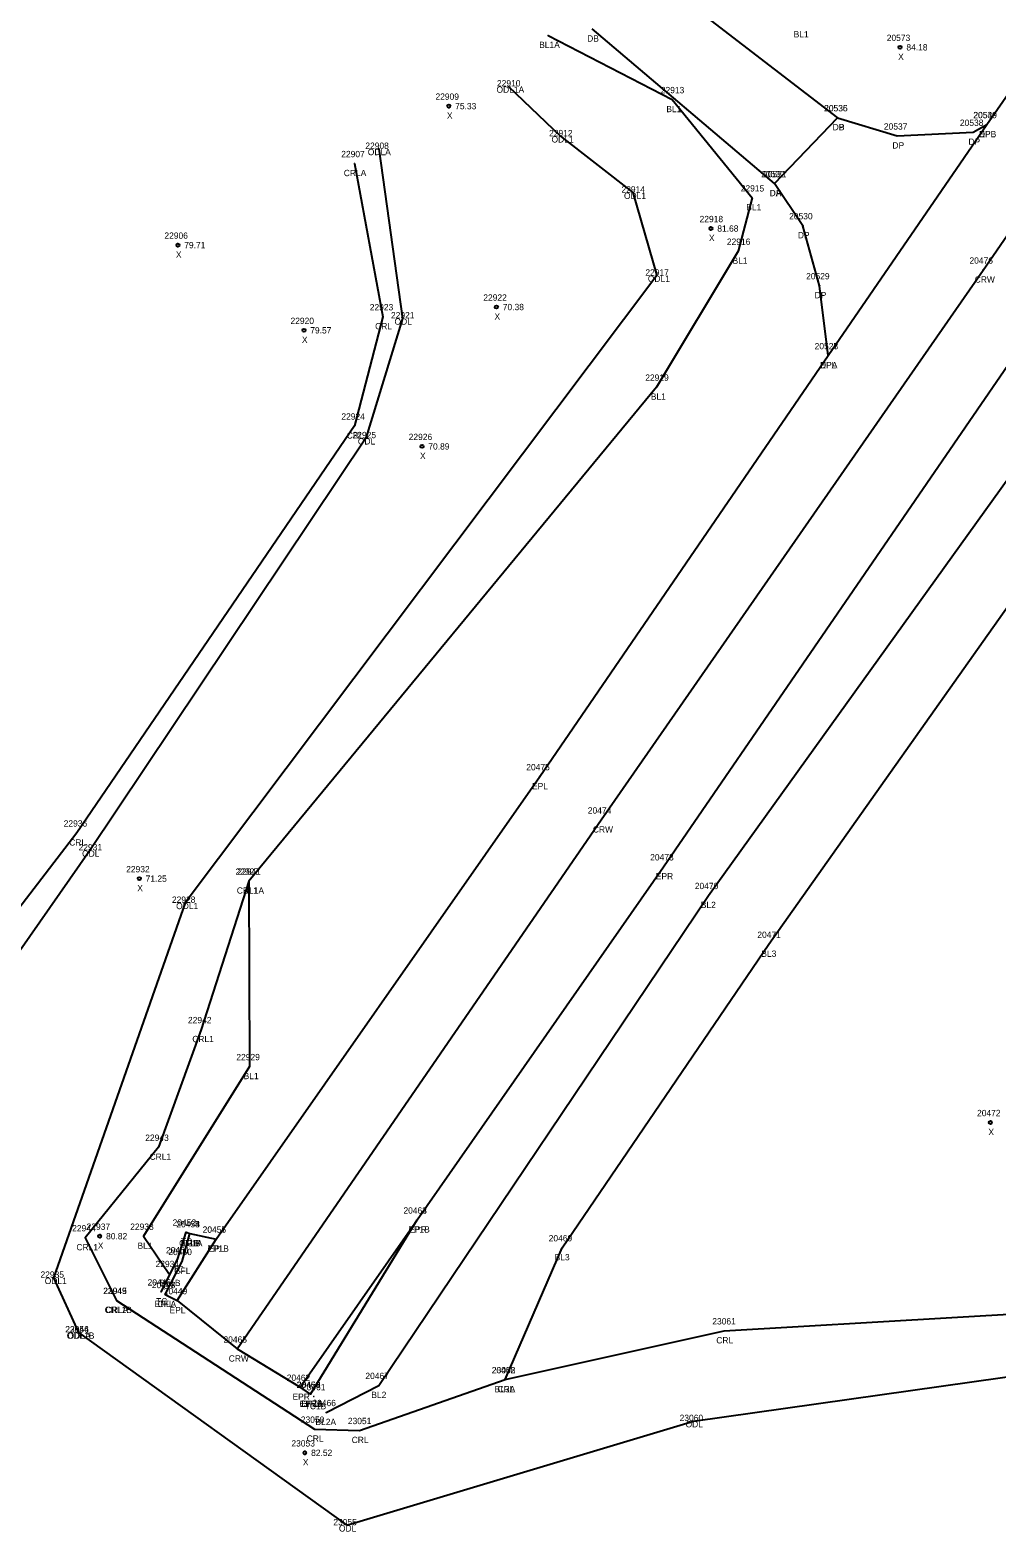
# Model space of a CAD drawing. Extents: x 2266664 to 2272385, y 716533 to 724777.
# Drawn here: x 2267635 to 2267788, y 717913.4 to 718152.1 of the extents above; entities that cross this region are included whole.
import ezdxf

# ---------------------------------------------------------------- set-up
doc = ezdxf.new("R2010")
doc.units = 0
for name, color, linetype in [('RD_DTM_BkLn1', 7, 'Continuous'), ('RD_DTM_BkLn2', 7, 'Continuous'), ('RD_EX_Conc', 7, 'Continuous'), ('RD_EX_Conc_txCode', 7, 'Continuous'), ('RD_EX_Driveway', 7, 'Continuous'), ('RD_EX_Driveway_txCode', 7, 'Continuous'), ('RD_EX_H2O', 7, 'Continuous'), ('RD_EX_H2O_txCode', 7, 'Continuous'), ('RD_EX_Road', 7, 'Continuous'), ('RD_EX_Road_txCode', 7, 'Continuous'), ('RD_Sketch8', 7, 'Continuous'), ('RD_SMD_Locator', 7, 'Continuous'), ('RD_SMD_Misc', 7, 'Continuous')]:
    doc.layers.add(name, color=color, linetype=linetype)

msp = doc.modelspace()

# ---------------------------------------------------------------- linework, layer by layer
at = {"layer": 'RD_DTM_BkLn1'}
for points in [[(2267710.19, 717938.44), (2267719.21, 717959.32), (2267751.93, 718007.38), (2267794.35, 718067.43), (2267822.53, 718077), (2267842.49, 718100.88), (2267841.99, 718104.19), (2267844.77, 718116), (2267850.84, 718142.33), (2267856.09, 718149.45), (2267873.81, 718175.89), (2267927.8, 718259.2), (2267986.43, 718342), (2268046.41, 718424.35), (2268102.94, 718500.87), (2268161.82, 718580.38), (2268222.22, 718658.4), (2268281.14, 718746.18), (2268334.54, 718833.88), (2268359.81, 718873.87), (2268370.29, 718889.66)], [(2267681.84, 717933.24), (2267690.2, 717937.53), (2267742.34, 718015.1), (2267802.82, 718099.26), (2267812.04, 718097.22), (2267823.3, 718090.87), (2267839.17, 718103.67), (2267824.81, 718121.31), (2267825.23, 718133.67), (2267861.61, 718184.44), (2267917.63, 718266.48), (2267975.71, 718350.02), (2268032.51, 718434.82), (2268088.99, 718510.9), (2268143.16, 718593.8), (2268201.81, 718676.06), (2268262.51, 718760.02), (2268318.82, 718844.76)], [(2267667.75, 717943.29), (2267725.37, 718027.06), (2267785.81, 718114.13), (2267843.43, 718197.83), (2267898.55, 718278.61), (2267956.82, 718362.94), (2268015.2, 718447.7), (2268070.98, 718528.34), (2268095.42, 718564.42)], [(2267716.97, 718151.28), (2267736.61, 718141.12), (2267749.26, 718125.56), (2267747.08, 718117.11), (2267734.15, 718095.59), (2267669.59, 718017.38), (2267669.72, 717988.01), (2267652.92, 717961.15), (2267656.93, 717955.25)], [(2267658.27, 717950.95), (2267667.75, 717943.29), (2267677.75, 717937.24)]]:
    msp.add_lwpolyline(points, dxfattribs=at)
at = {"layer": 'RD_DTM_BkLn2'}
msp.add_lwpolyline([(2267655.73, 717952.34), (2267658.34, 717957.44), (2267659.67, 717961.81), (2267660.25, 717961.55)], dxfattribs=at)
at = {"layer": 'RD_EX_Conc'}
msp.add_lwpolyline([(2267656.38, 717951.92), (2267659.04, 717957.15), (2267660.25, 717961.55)], dxfattribs=at)
at = {"layer": 'RD_EX_Driveway'}
for p, q in [((2267731.92, 718161.95), (2267762.79, 718138.25)), ((2267752.83, 718127.81), (2267723.94, 718152.29))]:
    msp.add_line(p, q, dxfattribs=at)
msp.add_lwpolyline([(2267761.28, 718100.58), (2267759.93, 718111.65), (2267757.28, 718121.15), (2267752.83, 718127.81), (2267762.79, 718138.25), (2267772.24, 718135.36), (2267784.27, 718135.95), (2267786.41, 718137.16)], dxfattribs=at)
at = {"layer": 'RD_EX_H2O'}
for points in [[(2267710.71, 718143.19), (2267718.93, 718135.31), (2267730.39, 718126.39), (2267734.17, 718113.25), (2267659.52, 718013.93), (2267638.72, 717954.57), (2267642.67, 717945.91)], [(2267690.17, 718133.31), (2267693.91, 718106.47), (2267688.11, 718087.5), (2267644.46, 718022.23), (2267586.58, 717939.31), (2267552.15, 717923.75), (2267514.13, 717905.59), (2267440.76, 717867.05), (2267355.07, 717819.56), (2267271.12, 717775.2), (2267212.59, 717739.65)], [(2267686.36, 718130.99), (2267690.83, 718106.74), (2267686.34, 718089.44), (2267642.41, 718025), (2267582.98, 717947.51), (2267550.82, 717926.2), (2267512.27, 717909.43), (2267438.37, 717872.3), (2267354.06, 717821.29), (2267269.27, 717778.74), (2267209.58, 717745.96)], [(2267669.59, 718017.38), (2267662.05, 717993.87), (2267655.29, 717975.24), (2267643.73, 717960.91), (2267648.67, 717950.99)], [(2267648.67, 717950.99), (2267680, 717930.6), (2267687.12, 717930.39), (2267710.19, 717938.44), (2267744.82, 717946.17), (2267816.91, 717950.39), (2267875.61, 717952.39), (2267928.18, 717957.12), (2267936.35, 717960.67), (2267968.01, 717966.35), (2267984.51, 717962.62), (2267996.02, 717960.08)], [(2267642.67, 717945.91), (2267685.11, 717915.38), (2267739.97, 717931.88), (2267818.36, 717942.95), (2267874.92, 717943.38), (2267931.69, 717954.3), (2267982.65, 717955.87), (2268023.68, 717902.48), (2268035.83, 717858.7), (2268110.12, 717741.99)]]:
    msp.add_lwpolyline(points, dxfattribs=at)
at = {"layer": 'RD_EX_Road'}
for p, q in [((2267679.35, 717936.13), (2267696.23, 717963.72)), ((2267660.25, 717961.55), (2267664.43, 717960.69))]:
    msp.add_line(p, q, dxfattribs=at)
for points in [[(2267656.38, 717951.92), (2267658.27, 717950.95), (2267664.43, 717960.69), (2267715.64, 718033.91), (2267761.28, 718100.58), (2267786.41, 718137.16), (2267833.26, 718204.57), (2267888.72, 718285.14), (2267947.43, 718370.13), (2268005.49, 718454.77), (2268062.35, 718536.98), (2268085.26, 718570.22), (2268085.68, 718570.9), (2268114.38, 718613.2), (2268130.13, 718635.29), (2268171.46, 718695.89), (2268186.85, 718718.09), (2268231.02, 718782.78), (2268287.66, 718866.23)], [(2267679.35, 717936.13), (2267677.75, 717937.24), (2267696.23, 717963.72), (2267735.24, 718019.64), (2267790.98, 718100.9), (2267816.93, 718136.13), (2267852.97, 718190.65), (2267908.9, 718272.41), (2267966.54, 718356.05), (2268024.65, 718440.27), (2268080.39, 718521.38), (2268105.01, 718557.4)]]:
    msp.add_lwpolyline(points, dxfattribs=at)
at = {"layer": 'RD_SMD_Locator'}
for centre, radius in [((2267716.97, 718151.28), 0.001), ((2267772.68, 718149.39), 0.25), ((2267710.71, 718143.19), 0.001), ((2267736.61, 718141.12), 0.001), ((2267701.27, 718140.08), 0.25), ((2267762.79, 718138.25), 0.001), ((2267762.79, 718138.25), 0.001), ((2267786.41, 718137.16), 0.001), ((2267786.41, 718137.16), 0.001), ((2267718.93, 718135.31), 0.001), ((2267772.24, 718135.36), 0.001), ((2267784.27, 718135.95), 0.001), ((2267690.17, 718133.31), 0.001), ((2267686.36, 718130.99), 0.001), ((2267752.83, 718127.81), 0.001), ((2267752.83, 718127.81), 0.001), ((2267730.39, 718126.39), 0.001), ((2267749.26, 718125.56), 0.001), ((2267742.75, 718120.7), 0.25), ((2267757.28, 718121.15), 0.001), ((2267658.39, 718118.07), 0.25), ((2267747.08, 718117.11), 0.001), ((2267734.17, 718113.25), 0.001), ((2267785.81, 718114.13), 0.001), ((2267759.93, 718111.65), 0.001), ((2267708.8, 718108.27), 0.25), ((2267690.83, 718106.74), 0.001), ((2267693.91, 718106.47), 0.001), ((2267678.33, 718104.58), 0.25), ((2267761.28, 718100.58), 0.001), ((2267761.28, 718100.58), 0.001), ((2267734.15, 718095.59), 0.001), ((2267686.34, 718089.44), 0.001), ((2267688.11, 718087.5), 0.001), ((2267697.02, 718086.2), 0.25), ((2267715.64, 718033.91), 0.001), ((2267725.37, 718027.06), 0.001), ((2267642.41, 718025), 0.001), ((2267644.46, 718022.23), 0.001), ((2267735.24, 718019.64), 0.001), ((2267652.28, 718017.76), 0.25), ((2267669.59, 718017.38), 0.001), ((2267669.59, 718017.38), 0.001), ((2267742.34, 718015.1), 0.001), ((2267659.52, 718013.93), 0.001), ((2267751.93, 718007.38), 0.001), ((2267662.05, 717993.87), 0.001), ((2267669.72, 717988.01), 0.001), ((2267786.98, 717979.15), 0.25), ((2267655.29, 717975.24), 0.001), ((2267696.23, 717963.72), 0.001), ((2267696.23, 717963.72), 0.001), ((2267643.73, 717960.91), 0.001), ((2267646.02, 717961.15), 0.25), ((2267652.92, 717961.15), 0.001), ((2267659.67, 717961.81), 0.001), ((2267660.25, 717961.55), 0.001), ((2267660.25, 717961.55), 0.001), ((2267660.25, 717961.55), 0.001), ((2267664.43, 717960.69), 0.001), ((2267664.43, 717960.69), 0.001), ((2267658.34, 717957.44), 0.001), ((2267719.21, 717959.32), 0.001), ((2267656.93, 717955.25), 0.001), ((2267659.04, 717957.15), 0.001), ((2267638.72, 717954.57), 0.001), ((2267648.67, 717950.99), 0.001), ((2267648.67, 717950.99), 0.001), ((2267655.73, 717952.34), 0.001), ((2267656.38, 717951.92), 0.001), ((2267656.38, 717951.92), 0.001), ((2267658.27, 717950.95), 0.001), ((2267642.67, 717945.91), 0.001), ((2267642.67, 717945.91), 0.001), ((2267744.82, 717946.17), 0.001), ((2267667.75, 717943.29), 0.001), ((2267710.19, 717938.44), 0.001), ((2267710.19, 717938.44), 0.001), ((2267677.75, 717937.24), 0.001), ((2267679.35, 717936.13), 0.001), ((2267679.35, 717936.13), 0.001), ((2267679.35, 717936.13), 0.001), ((2267690.2, 717937.53), 0.001), ((2267679.88, 717935.75), 0.001), ((2267681.84, 717933.24), 0.001), ((2267739.97, 717931.88), 0.001), ((2267680, 717930.6), 0.001), ((2267687.12, 717930.39), 0.001), ((2267678.47, 717926.85), 0.25), ((2267685.11, 717915.38), 0.001)]:
    msp.add_circle(centre, radius, dxfattribs=at)

# ---------------------------------------------------------------- texts
at = {"layer": 'RD_EX_Conc_txCode'}
for s, p in [('20454', (2267658.14, 717962.55)), ('CFLB', (2267658.58, 717959.55)), ('20450', (2267656.88, 717958.15)), ('CFL', (2267657.84, 717955.15)), ('20447', (2267654.26, 717952.92)), ('CFL', (2267655.18, 717949.92)), ('20458', (2267677.24, 717937.13)), ('CFRB', (2267677.65, 717934.13))]:
    msp.add_text(s, height=1, dxfattribs=at).set_placement(p)
at = {"layer": 'RD_EX_Driveway_txCode'}
for s, p in [('DB', (2267723.16, 718150.29)), ('20536', (2267760.65, 718139.25)), ('20535', (2267760.67, 718139.25)), ('20539', (2267784.29, 718138.16)), ('DB', (2267762.01, 718136.25)), ('DP', (2267762.01, 718136.25)), ('20537', (2267770.12, 718136.36)), ('20538', (2267782.15, 718136.95)), ('DP', (2267771.46, 718133.36)), ('DP', (2267783.49, 718133.95)), ('DPB', (2267785.16, 718135.16)), ('20532', (2267750.71, 718128.81)), ('20531', (2267750.99, 718128.81)), ('DA', (2267752.03, 718125.81)), ('DP', (2267752.05, 718125.81)), ('20530', (2267755.12, 718122.15)), ('DP', (2267756.5, 718119.15)), ('20529', (2267757.81, 718112.65)), ('DP', (2267759.15, 718109.65)), ('20528', (2267759.16, 718101.58)), ('DPA', (2267760.01, 718098.58))]:
    msp.add_text(s, height=1, dxfattribs=at).set_placement(p)
at = {"layer": 'RD_EX_H2O_txCode'}
for s, p in [('22910', (2267708.88, 718143.19)), ('ODL1A', (2267708.81, 718142.19)), ('22912', (2267717.13, 718135.31)), ('22908', (2267688.05, 718133.31)), ('ODL1', (2267717.52, 718134.31)), ('22907', (2267684.24, 718131.99)), ('ODLA', (2267688.44, 718132.31)), ('CRLA', (2267684.64, 718128.99)), ('22914', (2267728.59, 718126.39)), ('ODL1', (2267728.98, 718125.39)), ('22917', (2267732.37, 718113.25)), ('ODL1', (2267732.76, 718112.25)), ('22923', (2267688.75, 718107.74)), ('CRL', (2267689.6, 718104.74)), ('22921', (2267692.11, 718106.47)), ('ODL', (2267692.67, 718105.47)), ('22924', (2267684.26, 718090.44)), ('CRL', (2267685.11, 718087.44)), ('22925', (2267686.03, 718087.5)), ('ODL', (2267686.87, 718086.5)), ('22936', (2267640.31, 718026)), ('CRL', (2267641.18, 718023)), ('22931', (2267642.67, 718022.23)), ('ODL', (2267643.22, 718021.23)), ('22941', (2267667.79, 718018.38)), ('22928', (2267657.44, 718013.93)), ('CRL1A', (2267667.71, 718015.38)), ('ODL1', (2267658.11, 718012.93)), ('22942', (2267659.98, 717994.87)), ('CRL1', (2267660.66, 717991.87)), ('22943', (2267653.22, 717976.24)), ('CRL1', (2267653.9, 717973.24)), ('22944', (2267641.65, 717961.91)), ('CRL1', (2267642.33, 717958.91)), ('22935', (2267636.64, 717954.57)), ('ODL1', (2267637.31, 717953.57)), ('23049', (2267646.55, 717951.99)), ('22945', (2267646.59, 717951.99)), ('CRL1B', (2267646.8, 717948.99)), ('CRLA', (2267646.95, 717948.99)), ('23061', (2267742.96, 717947.17)), ('23054', (2267640.55, 717945.91)), ('22946', (2267640.57, 717945.91)), ('ODL1B', (2267640.79, 717944.91)), ('ODLA', (2267640.94, 717944.91)), ('CRL', (2267743.59, 717944.17)), ('23052', (2267708.08, 717939.44)), ('CRL', (2267708.97, 717936.44)), ('23050', (2267677.84, 717931.6)), ('23051', (2267685.28, 717931.39)), ('23060', (2267737.79, 717931.88)), ('ODL', (2267738.73, 717930.88)), ('CRL', (2267678.77, 717928.6)), ('CRL', (2267685.89, 717928.39)), ('23055', (2267682.99, 717915.38)), ('ODL', (2267683.87, 717914.38))]:
    msp.add_text(s, height=1, dxfattribs=at).set_placement(p)
at = {"layer": 'RD_EX_Road_txCode'}
for s, p in [('20540', (2267784.26, 718138.16)), ('EPL', (2267785.21, 718135.16)), ('20527', (2267759.16, 718101.58)), ('EPL', (2267760.07, 718098.58)), ('20475', (2267713.52, 718034.91)), ('EPL', (2267714.43, 718031.91)), ('20473', (2267733.13, 718020.64)), ('EPR', (2267734.02, 718017.64)), ('20463', (2267694.08, 717964.72)), ('20464', (2267694.08, 717964.72)), ('20455', (2267658.14, 717962.55)), ('20456', (2267662.29, 717961.69)), ('20457', (2267662.31, 717961.69)), ('EP1B', (2267694.83, 717961.72)), ('EPR', (2267695, 717961.72)), ('EP1A', (2267658.84, 717959.55)), ('EP1B', (2267663.03, 717958.69)), ('EPL', (2267663.22, 717958.69)), ('20448', (2267654.26, 717952.92)), ('20449', (2267656.15, 717951.95)), ('EPLA', (2267654.69, 717949.92)), ('EPL', (2267657.06, 717948.95)), ('20462', (2267675.61, 717938.24)), ('EPR', (2267676.52, 717935.24)), ('20460', (2267677.17, 717937.13)), ('20459', (2267677.24, 717937.13)), ('EPRA', (2267677.64, 717934.13)), ('EP1A', (2267677.94, 717934.13))]:
    msp.add_text(s, height=1, dxfattribs=at).set_placement(p)
at = {"layer": 'RD_Sketch8'}
for s, p in [('20573', (2267770.57, 718150.39)), ('X', (2267772.37, 718147.39)), ('84.18', (2267773.68, 718148.89)), ('22909', (2267699.15, 718141.08)), ('X', (2267700.96, 718138.08)), ('75.33', (2267702.27, 718139.58)), ('22918', (2267740.95, 718121.7)), ('22906', (2267656.25, 718119.07)), ('X', (2267742.43, 718118.7)), ('81.68', (2267743.75, 718120.2)), ('79.71', (2267659.39, 718117.57)), ('X', (2267658.07, 718116.07)), ('22922', (2267706.72, 718109.27)), ('70.38', (2267709.8, 718107.77)), ('22920', (2267676.21, 718105.58)), ('X', (2267708.49, 718106.27)), ('X', (2267678.01, 718102.58)), ('79.57', (2267679.33, 718104.08)), ('22926', (2267694.91, 718087.2)), ('70.89', (2267698.02, 718085.7)), ('X', (2267696.7, 718084.2)), ('22932', (2267650.2, 718018.76)), ('71.25', (2267653.28, 718017.26)), ('X', (2267651.96, 718015.76)), ('20472', (2267784.86, 717980.15)), ('X', (2267786.66, 717977.15)), ('22937', (2267643.94, 717962.15)), ('X', (2267645.71, 717959.15)), ('80.82', (2267647.02, 717960.65)), ('23053', (2267676.35, 717927.85)), ('82.52', (2267679.47, 717926.35)), ('X', (2267678.16, 717924.85))]:
    msp.add_text(s, height=1, dxfattribs=at).set_placement(p)
at = {"layer": 'RD_SMD_Misc'}
for s, p in [('BL1', (2267755.84, 718150.95)), ('BL1A', (2267715.56, 718149.28)), ('22913', (2267734.81, 718142.12)), ('BL1', (2267735.69, 718139.12)), ('22915', (2267747.46, 718126.56)), ('BL1', (2267748.34, 718123.56)), ('22916', (2267745.27, 718118.11)), ('BL1', (2267746.16, 718115.11)), ('20476', (2267783.66, 718115.13)), ('CRW', (2267784.49, 718112.13)), ('22919', (2267732.35, 718096.59)), ('BL1', (2267733.23, 718093.59)), ('20474', (2267723.26, 718028.06)), ('CRW', (2267724.06, 718025.06)), ('22927', (2267667.51, 718018.38)), ('20470', (2267740.19, 718016.1)), ('BL1', (2267668.67, 718015.38)), ('BL2', (2267741.14, 718013.1)), ('20471', (2267750.09, 718008.38)), ('BL3', (2267750.72, 718005.38)), ('22929', (2267667.64, 717989.01)), ('BL1', (2267668.79, 717986.01)), ('22933', (2267650.84, 717962.15)), ('20452', (2267657.55, 717962.81)), ('20453', (2267658.14, 717962.55)), ('BL1', (2267651.99, 717959.15)), ('TC', (2267658.87, 717959.81)), ('TCB', (2267658.99, 717959.55)), ('20469', (2267717.07, 717960.32)), ('22934', (2267654.85, 717956.25)), ('20451', (2267656.5, 717958.44)), ('BL3', (2267718.01, 717957.32)), ('TC', (2267657.54, 717955.44)), ('20446', (2267653.59, 717953.34)), ('BL1B', (2267655.53, 717953.25)), ('TC', (2267654.93, 717950.34)), ('20465', (2267665.6, 717944.29)), ('CRW', (2267666.43, 717941.29)), ('20467', (2267688.06, 717938.53)), ('20468', (2267708.05, 717939.44)), ('20461', (2267678.02, 717936.75)), ('BL2', (2267689, 717935.53)), ('BL3A', (2267708.5, 717936.44)), ('TC1B', (2267678.45, 717933.75)), ('20466', (2267679.68, 717934.24)), ('BL2A', (2267680.15, 717931.24))]:
    msp.add_text(s, height=1, dxfattribs=at).set_placement(p)

doc.saveas('drawing.dxf')
